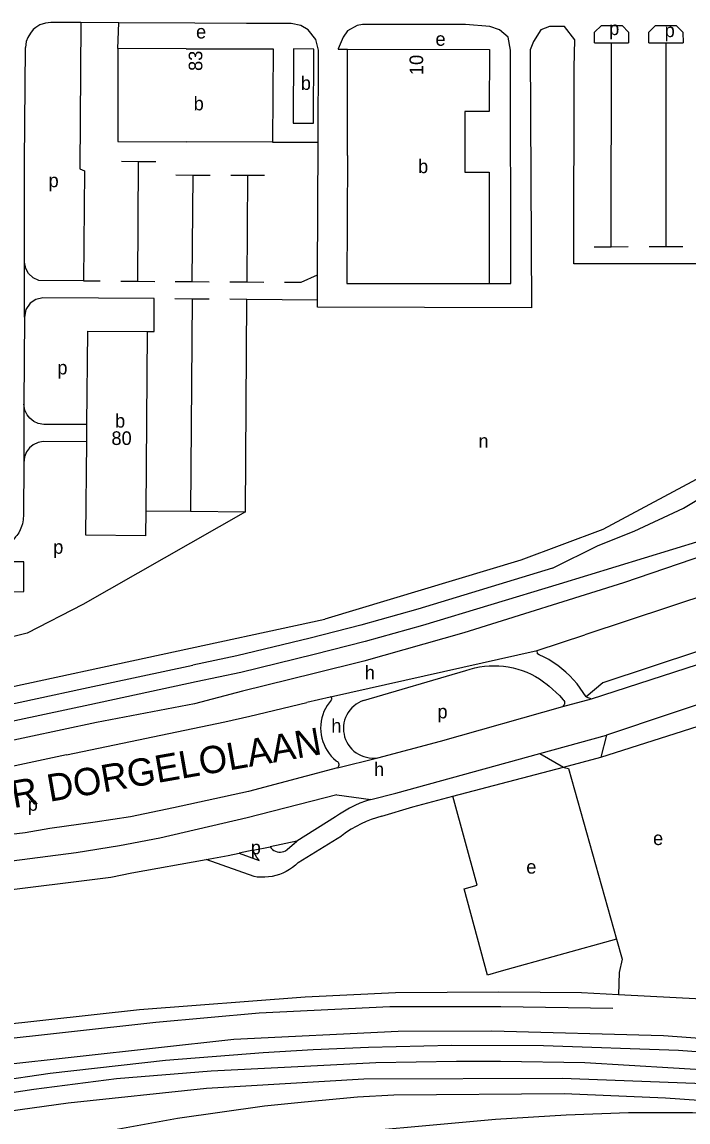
# Model space of a CAD drawing. Extents: x 161494 to 163033, y 383688 to 384862.
# Drawn here: x 162517.1 to 162712.5, y 384018.3 to 384341 of the extents above; entities that cross this region are included whole.
import ezdxf

# ---------------------------------------------------------------- set-up
doc = ezdxf.new("R2010")
doc.units = 0
for name, color, linetype in [('BLT_Basislijn', 7, 'Continuous'), ('BLT_Bebouwing', 7, 'Continuous'), ('BLT_Centroide', 7, 'Continuous'), ('BLT_Huisnummer', 7, 'Continuous'), ('BLT_Spoorlijn', 7, 'Continuous'), ('BLT_Straatnaam_hoofdweg', 7, 'Continuous'), ('BLT_Vlakafsluiter', 7, 'Continuous')]:
    doc.layers.add(name, color=color, linetype=linetype)

msp = doc.modelspace()

# ---------------------------------------------------------------- linework, layer by layer
at = {"layer": 'BLT_Basislijn'}
for p, q in [((162545.27, 384333.18), (162545.55, 384340.76)), ((162685.05, 384334.85), (162690.06, 384334.84)), ((162689.99, 384274.96), (162690.06, 384334.84)), ((162690.06, 384334.84), (162695.07, 384334.84)), ((162701.04, 384334.86), (162706.05, 384334.85)), ((162706.05, 384334.85), (162711.06, 384334.85)), ((162706.05, 384334.85), (162706.05, 384274.98)), ((162590.59, 384305.75), (162603.99, 384305.7)), ((162546.31, 384300.16), (162551.32, 384300.1)), ((162551.08, 384264.94), (162551.32, 384300.1)), ((162551.32, 384300.1), (162556.34, 384300.05)), ((162562.29, 384296.11), (162567.29, 384296.08)), ((162567.06, 384264.81), (162567.29, 384296.08)), ((162567.29, 384296.08), (162572.3, 384296.05)), ((162578.35, 384296.02), (162583.32, 384296.04)), ((162583.32, 384296.04), (162583.07, 384264.73)), ((162583.32, 384296.04), (162588.28, 384296.06)), ((162517.89, 384270.52), (162517.89, 384292.56)), ((162689.99, 384274.96), (162685, 384274.95)), ((162694.97, 384274.97), (162689.99, 384274.96)), ((162706.05, 384274.98), (162701.09, 384274.98)), ((162711.01, 384274.97), (162706.05, 384274.98)), ((162517.82, 384254.43), (162517.89, 384270.52)), ((162535.13, 384265.07), (162540.05, 384265.02)), ((162546.1, 384264.99), (162551.08, 384264.94)), ((162551.08, 384264.94), (162556.07, 384264.89)), ((162562.08, 384264.86), (162567.06, 384264.81)), ((162567.06, 384264.81), (162572.04, 384264.76)), ((162578.07, 384264.76), (162583.07, 384264.73)), ((162583.07, 384264.73), (162588.07, 384264.7)), ((162561.99, 384259.83), (162566.99, 384259.79)), ((162566.99, 384259.79), (162566.52, 384197.43)), ((162566.99, 384259.79), (162571.99, 384259.76)), ((162578.05, 384259.72), (162583.06, 384259.69)), ((162582.67, 384197.29), (162583.06, 384259.69)), ((162517.82, 384254.43), (162517.64, 384228.83)), ((162517.64, 384228.83), (162517.61, 384211.61)), ((162711.22, 384198.35), (162744.58, 384218.73)), ((162566.52, 384197.43), (162582.67, 384197.29)), ((162663.49, 384183.13), (162605.96, 384165.77)), ((162672.79, 384180.71), (162633.21, 384168.77)), ((162727.04, 384176.07), (162682.21, 384161.19)), ((162455.1, 384133.3), (162605.96, 384165.77)), ((162668.23, 384156.58), (162682.21, 384161.19)), ((162686.99, 384125.31), (162796.88, 384160.38)), ((162668.33, 384155.62), (162668.23, 384156.58)), ((162535.12, 384145.41), (162567.23, 384152.32)), ((162617.35, 384141.93), (162647.29, 384150.72)), ((162607.5, 384142.94), (162600.73, 384141.32)), ((162607.64, 384142.97), (162607.5, 384142.94)), ((162688.65, 384131.73), (162686.99, 384125.31)), ((162626.78, 384114.78), (162669.03, 384126.37)), ((162669.03, 384126.37), (162675.96, 384122.4)), ((162675.96, 384122.4), (162686.99, 384125.31)), ((162643.52, 384113.83), (162675.96, 384122.4)), ((162675.96, 384122.4), (162676.18, 384122.27)), ((162619.49, 384112.91), (162626.78, 384114.78)), ((162631.81, 384110.74), (162643.52, 384113.83)), ((162622.67, 384108), (162631.81, 384110.74)), ((162609.06, 384107.77), (162597.74, 384100.68)), ((162584.9, 384098.01), (162589.91, 384099.05)), ((162598.18, 384094.38), (162610.85, 384102.19)), ((162549.36, 384091.36), (162571.17, 384095.32)), ((162585.24, 384090.25), (162571.17, 384095.32)), ((162716.59, 384054.27), (162692.1, 384055.57)), ((162551.62, 384051.16), (162505.86, 384046.13))]:
    msp.add_line(p, q, dxfattribs=at)
for points in [[(162656.92, 384488.75), (162691.6, 384496.32), (162752.47, 384384.97), (162757.12, 384375.47), (162784.76, 384290.27), (162786.79, 384281.41), (162786.93, 384272.34), (162783.57, 384261.18), (162776.08, 384247.54), (162769.02, 384241.88), (162719.16, 384209.03), (162687.54, 384192.14), (162663.49, 384183.13)], [(162722.09, 384345.95), (162727.84, 384345.96), (162731.62, 384343.88), (162733.05, 384339.81), (162733.14, 384334.84), (162738.07, 384334.83), (162738.03, 384269.99), (162679.07, 384270.05), (162679.11, 384327.6), (162679.27, 384335.75), (162676.27, 384339.62), (162671.85, 384339.62)], [(162534.33, 384340.79), (162525.58, 384340.8), (162524.05, 384340.65), (162522.39, 384340.1), (162521.19, 384339.38), (162520.42, 384338.73), (162519.57, 384337.74), (162518.8, 384336.42), (162518.35, 384335.21), (162518.12, 384333.5)], [(162534.33, 384340.79), (162534.03, 384297.88), (162535.42, 384297.29), (162535.13, 384265.07)], [(162545.55, 384340.76), (162534.33, 384340.79)], [(162603.99, 384305.7), (162604.09, 384332.73), (162603.28, 384335.89), (162601.1, 384338.69), (162598.91, 384339.94), (162596.11, 384340.56), (162590.81, 384340.56), (162582.95, 384340.53), (162567.82, 384340.63), (162545.55, 384340.76)], [(162654.15, 384264.29), (162660.52, 384264.28), (162660.46, 384332.72), (162659.71, 384336.51), (162657.22, 384338.69), (162654.41, 384339.63), (162647.24, 384340.25), (162622.92, 384340.25), (162617, 384340.25), (162615.44, 384339.94), (162612.63, 384338.38), (162611.39, 384336.51), (162609.83, 384333.08), (162609.83, 384333.03), (162612.66, 384333.02)], [(162671.85, 384339.62), (162669.38, 384338.69), (162667.2, 384335.26), (162666.26, 384332.77), (162666.57, 384257.08)], [(162685.05, 384334.85), (162685.09, 384337.97), (162687.15, 384339.95), (162693.16, 384339.95), (162695.11, 384337.97), (162695.07, 384334.84)], [(162701.04, 384334.86), (162701.03, 384337.97), (162703.01, 384339.97), (162709.03, 384339.98), (162711.03, 384337.97), (162711.06, 384334.85)], [(162517.86, 384297.56), (162517.84, 384300), (162518.12, 384333.5)], [(162603.84, 384266.79), (162603.99, 384305.7)], [(162517.89, 384292.56), (162517.86, 384297.56)], [(162535.13, 384265.07), (162522, 384265.19), (162520.4, 384265.9), (162519.04, 384267.15), (162518.23, 384268.63), (162517.89, 384270.52)], [(162594.11, 384264.65), (162599.04, 384264.61), (162603.84, 384266.79)], [(162603.81, 384259.51), (162603.84, 384266.79)], [(162553.88, 384250.2), (162555.86, 384250.19), (162555.93, 384259.85), (162523.18, 384260.1), (162521.2, 384259.6), (162519.53, 384258.45), (162518.28, 384256.61), (162517.82, 384254.43)], [(162583.06, 384259.69), (162603.81, 384259.51)], [(162603.8, 384257.29), (162603.81, 384259.51)], [(162666.57, 384257.08), (162603.8, 384257.29)], [(162536.16, 384222.85), (162523.47, 384222.93), (162521.9, 384223.21), (162520.6, 384223.79), (162519.41, 384224.73), (162518.59, 384225.75), (162517.94, 384227.12), (162517.64, 384228.83)], [(162536.12, 384217.85), (162523.35, 384217.91), (162521.86, 384217.63), (162520.42, 384216.95), (162519.35, 384216.07), (162518.45, 384214.91), (162517.82, 384213.41), (162517.61, 384211.61)], [(162517.61, 384211.61), (162517.58, 384196.53), (162517.49, 384194.95), (162517.26, 384193.77), (162517.01, 384192.99), (162516.54, 384191.95), (162516.21, 384191.16), (162515.62, 384190.32), (162515.24, 384189.97), (162514.68, 384189.27), (162514.02, 384188.69), (162513.3, 384188.16), (162512.44, 384187.63), (162511.53, 384187.19), (162510.1, 384186.7)], [(162776.38, 384206.12), (162759.39, 384199.14), (162734, 384190.26), (162693.61, 384176.48), (162646.79, 384161.78), (162617.42, 384153.51)], [(162582.67, 384197.29), (162534.92, 384170.11), (162518.61, 384161.72), (162495.34, 384155.87), (162488.64, 384155.57)], [(162553.42, 384197.55), (162566.52, 384197.43)], [(162672.79, 384180.71), (162686.15, 384187.42), (162696.72, 384191.56), (162711.22, 384198.35)], [(162716.24, 384188.77), (162674.69, 384176.06), (162634.6, 384163.96)], [(162633.21, 384168.77), (162616.54, 384164.04), (162601.64, 384160.24), (162580.17, 384155.06), (162567.23, 384152.32)], [(162634.6, 384163.96), (162617.84, 384159.22), (162602.85, 384155.39), (162581.27, 384150.18), (162568.26, 384147.43)], [(162682.63, 384142.96), (162681.81, 384144.3), (162680.91, 384145.58), (162679.96, 384146.82), (162678.94, 384148.01), (162677.86, 384149.15), (162676.72, 384150.23), (162675.53, 384151.25), (162674.29, 384152.2), (162673.01, 384153.1), (162671.67, 384153.92), (162670.3, 384154.68), (162668.89, 384155.37), (162668.33, 384155.62)], [(162715.59, 384156.44), (162687.56, 384147.15), (162682.63, 384142.96)], [(162760.16, 384156.84), (162726.82, 384144.61), (162688.65, 384131.73)], [(162617.42, 384153.51), (162602.88, 384149.84), (162581.77, 384144.63), (162567.69, 384140.96), (162538.93, 384135.45), (162508.64, 384129.02)], [(162647.29, 384150.72), (162648.64, 384151.16), (162650, 384151.51), (162651.38, 384151.79), (162652.78, 384151.99), (162654.18, 384152.1), (162655.59, 384152.14), (162657, 384152.1), (162658.4, 384151.98), (162659.8, 384151.78), (162661.18, 384151.5), (162662.55, 384151.14), (162663.89, 384150.71), (162665.2, 384150.2), (162666.49, 384149.62), (162667.73, 384148.96), (162668.94, 384148.24), (162670.11, 384147.45), (162671.23, 384146.59), (162671.79, 384146.12)], [(162455.1, 384133.3), (162455.17, 384129), (162486.94, 384135.33), (162507.91, 384139.6), (162535.12, 384145.41)], [(162568.26, 384147.43), (162536.97, 384140.69), (162508.97, 384134.72)], [(162671.79, 384146.12), (162674.78, 384143.39), (162675.93, 384142.14)], [(162530.17, 384125.97), (162576.65, 384135.68), (162583.97, 384137.38), (162600.73, 384141.32)], [(162607.83, 384142.06), (162607.2, 384141.28), (162606.64, 384140.46), (162606.15, 384139.6), (162605.72, 384138.69), (162605.37, 384137.76), (162605.1, 384136.8), (162604.9, 384135.82), (162604.78, 384134.83), (162604.74, 384133.84), (162604.78, 384132.84), (162604.9, 384131.85), (162605.11, 384130.87), (162605.38, 384129.92), (162605.74, 384128.98), (162606.16, 384128.08), (162606.66, 384127.22), (162607.23, 384126.4), (162607.86, 384125.63), (162608.55, 384124.91), (162609.29, 384124.24), (162609.38, 384124.17)], [(162607.83, 384142.06), (162607.97, 384142.19), (162608.05, 384142.37), (162608.05, 384142.56), (162607.98, 384142.74), (162607.83, 384142.88), (162607.64, 384142.97)], [(162617.35, 384141.93), (162616.57, 384141.63), (162615.83, 384141.25), (162615.12, 384140.81), (162614.46, 384140.3), (162613.86, 384139.73), (162613.31, 384139.1), (162612.82, 384138.43), (162612.4, 384137.71), (162612.06, 384136.95), (162611.78, 384136.17), (162611.58, 384135.36), (162611.46, 384134.54), (162611.42, 384133.71), (162611.46, 384132.87), (162611.59, 384132.05), (162611.78, 384131.24), (162612.06, 384130.46), (162612.41, 384129.7), (162612.83, 384128.98), (162613.32, 384128.31), (162613.87, 384127.68), (162614.47, 384127.11), (162615.13, 384126.61), (162615.84, 384126.16), (162616.58, 384125.79), (162617.36, 384125.49), (162618.16, 384125.26), (162618.98, 384125.12), (162619.81, 384125.05), (162620.64, 384125.06), (162621.47, 384125.14)], [(162675.93, 384142.14), (162676.13, 384141.89), (162676.26, 384141.61), (162676.31, 384141.3), (162676.28, 384140.99), (162676.18, 384140.7), (162676, 384140.44), (162675.77, 384140.21)], [(162621.47, 384125.14), (162639.91, 384129.99), (162675.77, 384140.21)], [(162530.17, 384125.97), (162500.45, 384119.61), (162479.46, 384115.38), (162463.55, 384112.14)], [(162609.67, 384122.13), (162583.55, 384115.27), (162561.58, 384110.48), (162548.9, 384107.8), (162538.62, 384106.25), (162525.24, 384104.42)], [(162609.38, 384124.17), (162609.64, 384124.03), (162609.86, 384123.82), (162610.01, 384123.56), (162610.09, 384123.27), (162610.09, 384122.96), (162610.02, 384122.67), (162609.87, 384122.41), (162609.67, 384122.13)], [(162676.18, 384122.27), (162677.49, 384121.98), (162691.56, 384071.88)], [(162609.51, 384114.25), (162583.17, 384107.55), (162557.51, 384101.52), (162545.68, 384099.29), (162532.96, 384097.28), (162511.09, 384094.38), (162474.93, 384090.36)], [(162619.49, 384112.91), (162617.87, 384112.38), (162616.28, 384111.77), (162614.72, 384111.08), (162613.2, 384110.32), (162611.71, 384109.49), (162610.26, 384108.59), (162609.06, 384107.77)], [(162691.56, 384071.88), (162657.67, 384062.51), (162653.72, 384061.39), (162646.87, 384086.64), (162650.7, 384087.8), (162643.52, 384113.83)], [(162622.67, 384108), (162621.11, 384107.55), (162619.57, 384107.02), (162618.06, 384106.42), (162616.58, 384105.74), (162615.13, 384105), (162613.73, 384104.18), (162612.36, 384103.29), (162611.04, 384102.34), (162610.85, 384102.19)], [(162525.24, 384104.42), (162518.05, 384103.12), (162499.04, 384100.87), (162472.56, 384097.77), (162460.59, 384096.36)], [(162597.74, 384100.68), (162589.91, 384099.05)], [(162589.91, 384099.05), (162590.21, 384098.63), (162590.57, 384098.26), (162590.99, 384097.94), (162591.45, 384097.7), (162591.94, 384097.53), (162592.45, 384097.43), (162592.97, 384097.42), (162593.48, 384097.49), (162593.98, 384097.63), (162594.45, 384097.85), (162594.95, 384098.19), (162597.74, 384100.68)], [(162571.17, 384095.32), (162577.65, 384096.5), (162580.82, 384097.16)], [(162584.9, 384098.01), (162580.82, 384097.16)], [(162580.82, 384097.16), (162586.73, 384095.02), (162586.56, 384095.21), (162586.04, 384095.84), (162585.59, 384096.53), (162585.21, 384097.25), (162584.9, 384098.01)], [(162598.18, 384094.38), (162597.37, 384093.64), (162596.5, 384092.96), (162595.59, 384092.34), (162594.64, 384091.8), (162593.65, 384091.32), (162592.62, 384090.92), (162591.57, 384090.59), (162590.5, 384090.34), (162589.42, 384090.17), (162588.32, 384090.08), (162587.22, 384090.07), (162586.12, 384090.13), (162585.24, 384090.25)], [(162498.03, 384084.42), (162507.74, 384085.67), (162543.22, 384090.13), (162549.36, 384091.36)], [(162691.56, 384071.88), (162693.2, 384066.07), (162692.37, 384062.12), (162692.1, 384055.57)], [(162692.1, 384055.57), (162681.25, 384056.14), (162656.98, 384056.35), (162626.7, 384056.14), (162600.15, 384054.89), (162551.62, 384051.16)], [(162184.97, 383975.01), (162234.27, 383985.59), (162280.45, 383994.61), (162317.07, 384003.01), (162357.89, 384012.37), (162415.17, 384024.78), (162473.52, 384036.49), (162505.94, 384041.95), (162556.37, 384047.61), (162586.74, 384050.32), (162625.03, 384052.18), (162657.62, 384052.19), (162690.5, 384051.66)], [(162956.78, 384021.72), (162940.81, 384022.86), (162844.13, 384032.25), (162776, 384038.39), (162705.31, 384043.59), (162655, 384044.9), (162627.45, 384044.8), (162579.26, 384042.49), (162510.26, 384034.87), (162452.51, 384024.7), (162377.46, 384008.85), (162301.58, 383991.65), (162233.15, 383976.81), (162161.35, 383961.08), (162082.65, 383946.35), (162000.1, 383931.74), (161945.86, 383921.22), (161938.95, 383921.37)]]:
    msp.add_lwpolyline(points, dxfattribs=at)
at = {"layer": 'BLT_Bebouwing'}
for p, q in [((162545.27, 384333.18), (162545.25, 384305.95)), ((162565.24, 384333.14), (162545.27, 384333.18))]:
    msp.add_line(p, q, dxfattribs=at)
for points in [[(162565.24, 384333.14), (162590.8, 384333.08), (162590.59, 384305.75)], [(162612.57, 384301.82), (162612.66, 384333.02)], [(162612.66, 384333.02), (162654.28, 384332.89), (162654.22, 384314.7), (162647.02, 384314.72), (162647.02, 384296.92), (162654.18, 384296.92), (162654.15, 384264.29)], [(162545.25, 384305.95), (162565.25, 384305.86)], [(162590.59, 384305.75), (162565.25, 384305.86)], [(162612.57, 384301.82), (162612.38, 384264.31)], [(162612.38, 384264.31), (162654.15, 384264.29)], [(162536.16, 384222.85), (162536.4, 384250.29), (162553.88, 384250.2)], [(162553.88, 384250.2), (162553.42, 384197.55)], [(162536.12, 384217.85), (162536.16, 384222.85)], [(162553.42, 384197.55), (162553.36, 384190.26), (162535.88, 384190.41), (162536.12, 384217.85)], [(162492.42, 384173.83), (162517.65, 384173.88), (162517.62, 384182.62), (162510.13, 384182.61)]]:
    msp.add_lwpolyline(points, dxfattribs=at)
msp.add_lwpolyline([(162602.76, 384333.04), (162596.76, 384333.07), (162596.66, 384311.28), (162602.65, 384311.26)], close=True, dxfattribs=at)
at = {"layer": 'BLT_Spoorlijn'}
for points in [[(162493.36, 384027.95), (162525.34, 384032.6), (162559.19, 384036.38), (162587.86, 384038.71), (162602.55, 384039.57), (162618.77, 384040.28), (162643.1, 384040.8), (162670.1, 384040.71)], [(162670.1, 384040.71), (162709.74, 384039.34), (162763.63, 384035.31), (162835.76, 384028.79), (162878.78, 384025.43)], [(162851.52, 384017.92), (162815.39, 384024.3), (162780.35, 384028.34), (162734.32, 384032.49), (162682.28, 384035.6), (162657.55, 384036.07), (162644.62, 384036.06), (162620.91, 384035.6), (162600, 384034.57), (162572.62, 384033.21), (162544.84, 384030.9), (162520.54, 384027.83), (162490.18, 384023.26), (162444.69, 384014.9), (162206.08, 383962.22), (162182.09, 383956.51), (162143.86, 383951.57)], [(162900.86, 384011.36), (162871.5, 384014.34), (162849.2, 384016.61), (162786.11, 384023.02), (162743.32, 384027.37), (162714.49, 384029.62), (162675.59, 384031.05), (162617.43, 384030.81), (162571.29, 384028.11), (162530.64, 384023.81), (162498.89, 384019.36), (162460.78, 384012.83), (162360.78, 383991.35), (162187.34, 383952.61), (162103.09, 383933.78), (162003.41, 383912.03), (161897.47, 383888.44), (161858.44, 383879.75), (161796.71, 383866.01)], [(162015.34, 383899.38), (162017.25, 383899.68), (162080.65, 383914.34), (162260.47, 383954.06), (162264.14, 383955.18), (162275.03, 383957.62), (162500.2, 384007.1), (162541.18, 384015.46), (162562.76, 384019.37), (162588.28, 384023.03), (162600, 384024.15), (162615.59, 384025.65), (162626.19, 384026.21), (162676.14, 384026.61), (162705.93, 384025.41), (162732.39, 384023.5), (162757.2, 384021.52), (162782.07, 384018.89)], [(162718.29, 384020.75), (162713.88, 384020.92), (162695.07, 384020.96), (162676.79, 384020.24), (162656.02, 384019.05), (162600, 384013.9), (162494.64, 384004.23)]]:
    msp.add_lwpolyline(points, dxfattribs=at)
at = {"layer": 'BLT_Vlakafsluiter'}
for p, q in [((162607.64, 384142.97), (162668.23, 384156.58)), ((162675.77, 384140.21), (162684.25, 384142.42)), ((162669.03, 384126.37), (162688.65, 384131.73)), ((162609.67, 384122.13), (162621.47, 384125.14)), ((162609.51, 384114.25), (162619.49, 384112.91))]:
    msp.add_line(p, q, dxfattribs=at)
for points in [[(162684.25, 384142.42), (162725.87, 384155.94)], [(162682.63, 384142.96), (162684.25, 384142.42)]]:
    msp.add_lwpolyline(points, dxfattribs=at)

# ---------------------------------------------------------------- texts
at = {"layer": 'BLT_Centroide'}
for s, p in [('e', (162568.18, 384336.14)), ('p', (162689.39, 384337.14)), ('p', (162705.67, 384336.54)), ('e', (162638.43, 384334)), ('b', (162598.91, 384321.05)), ('b', (162567.47, 384315.06)), ('b', (162633.33, 384296.64)), ('p', (162524.9, 384292.51)), ('p', (162527.48, 384237.59)), ('b', (162544.41, 384221.99)), ('n', (162651.05, 384216.08)), ('p', (162526.27, 384184.98)), ('h', (162617.68, 384148.12)), ('p', (162639.01, 384136.69)), ('h', (162607.86, 384132.53)), ('h', (162620.39, 384119.75)), ('p', (162518.79, 384109.58)), ('e', (162702.27, 384099.52)), ('p', (162584.23, 384096.82)), ('e', (162665.08, 384091.14))]:
    msp.add_text(s, height=4, dxfattribs=at).set_placement(p)
at = {"layer": 'BLT_Huisnummer'}
for s, rotation, p in [('83', 90.021, (162570.02, 384326.61)), ('10', 90.021, (162634.82, 384325.4)), ('80', 359.9937, (162543.35, 384216.89))]:
    msp.add_text(s, height=4, rotation=rotation, dxfattribs=at).set_placement(p)
at = {"layer": 'BLT_Straatnaam_hoofdweg'}
msp.add_text('PROFESSOR DR DORGELOLAAN', height=8, rotation=9.9281, dxfattribs=at).set_placement((162437.96, 384096.91))

doc.saveas('drawing.dxf')
